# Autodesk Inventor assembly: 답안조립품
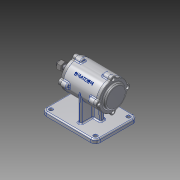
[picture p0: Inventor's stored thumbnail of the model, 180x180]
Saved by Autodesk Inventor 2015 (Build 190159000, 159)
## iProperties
Created: 2015-12
Part Number: 답안조립품
Document SubType Name: Assembly
Designer: 601-23
Author: 601-23
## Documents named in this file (10)
- C:\Users\601-23\Desktop\451208V1009\답안조립품.iam
- C:\Users\601-23\Desktop\451208V1009\본체.ipt
- C:\Users\601-23\Desktop\451208V1009\축.ipt
- C:\Users\601-23\Desktop\451208V1009\베어링 6204.ipt
- C:\Users\601-23\Desktop\451208V1009\커버2.ipt
- C:\Users\601-23\Desktop\451208V1009\커버.ipt
- C:\Users\601-23\Desktop\451208V1009\오일실.ipt
- C:\Users\601-23\Desktop\451208V1009\키(4 x 4 x 12).ipt
- C:\Users\601-23\Desktop\451208V1009\V-벨트풀리.ipt
- C:\Users\601-23\Desktop\451208V1009\너트 M12x1.25.ipt
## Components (6 placed, 5 different names)
1. KS B 2023 6204 - 20 x 47 x 14:1
2. KS B 2023 6204 - 20 x 47 x 14:2
3. KS B 2804 D D - 20 32 8:1
4. KS B 1311 (I) 4 x 4 x 12:1 — 각도:1
5. V-벨트풀리:1
6. KS B 1012 클래스 1 일반 - 미터 M12x1.25:1 — 각도:1
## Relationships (1: Angle 1)
- 각도:1 [Angle]: KS B 1311 (I) 4 x 4 x 12:1 ↔ KS B 1012 클래스 1 일반 - 미터 M12x1.25:1
